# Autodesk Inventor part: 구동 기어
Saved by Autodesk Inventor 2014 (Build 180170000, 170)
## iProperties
Created: 2025-12
Part Number: 구동 기어
Material: 일반
Document SubType Name: Modeling
Designer: dg
Density: 1 g/cm^3
Appearance: 기본값
Author: dg
Author: jhkim
Creation Date: 2025-11-19
Sending System: Autodesk Inventor 2026
Preprocessor: ST-DEVELOPER v20.1
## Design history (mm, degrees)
node "구동 기어1"
node "솔리드1"
node "기준1"
